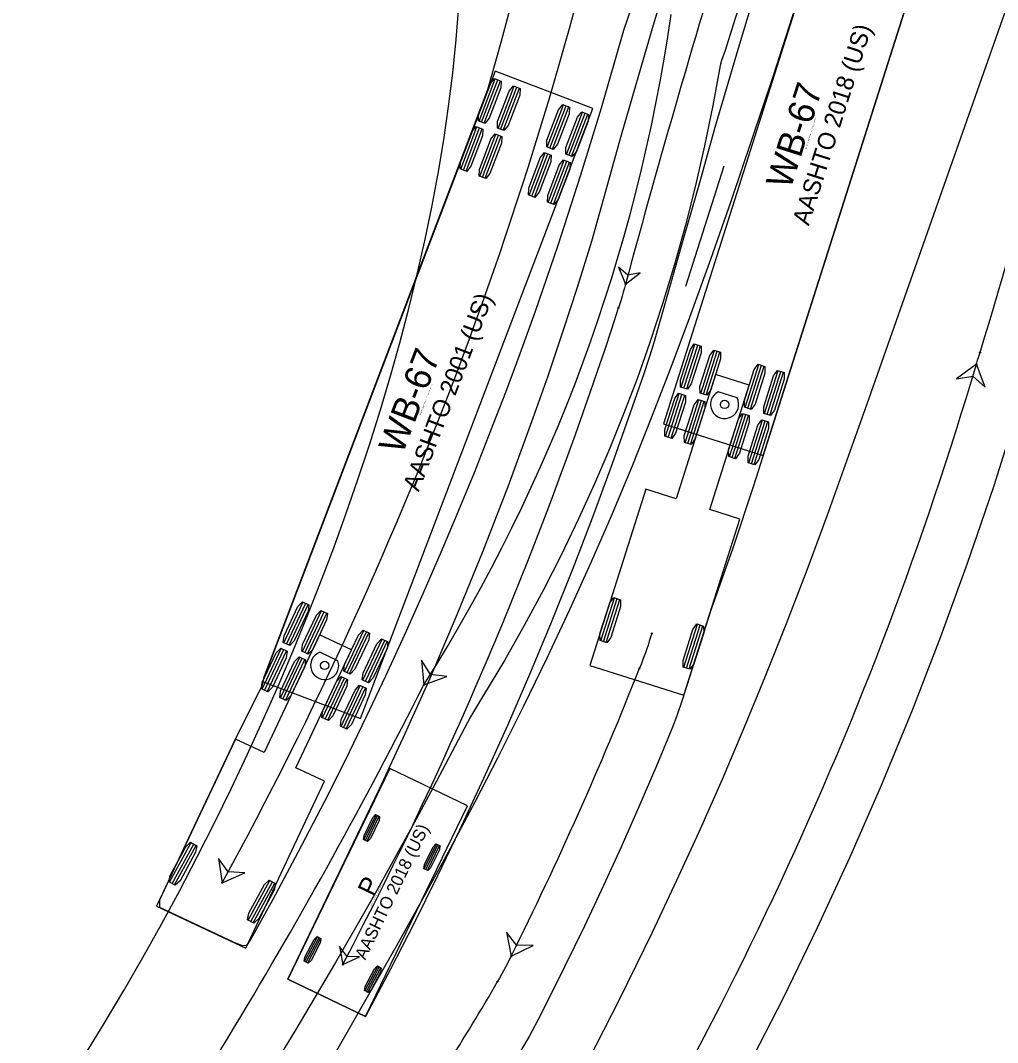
# Model space of a CAD drawing. Extents: x 2175591 to 2194071, y 76570 to 86955.
# Drawn here: x 2192866.1 to 2192945.4, y 86502.5 to 86585.5 of the extents above; entities that cross this region are included whole.
import ezdxf

# ---------------------------------------------------------------- set-up
doc = ezdxf.new("R2010")
doc.units = 0
doc.layers.add('-NOPLT', color=7, linetype='Continuous')
doc.layers.add('C-UTIL-STRM-TEXT', color=7, linetype='Continuous')

msp = doc.modelspace()

# ---------------------------------------------------------------- linework, layer by layer
at = {"layer": '-NOPLT'}
for p, q in [((2192934.321, 86603.271), (2192918.277, 86552.758)), ((2192926.378, 86550.185), (2192942.422, 86600.698)), ((2192919.723, 86555.726), (2192920.832, 86559.221)), ((2192919.941, 86555.657), (2192921.051, 86559.151)), ((2192920.159, 86555.587), (2192921.269, 86559.082)), ((2192921.295, 86555.227), (2192922.405, 86558.721)), ((2192921.514, 86555.157), (2192922.623, 86558.652)), ((2192921.732, 86555.088), (2192922.842, 86558.583)), ((2192924.901, 86554.081), (2192926.011, 86557.576)), ((2192925.119, 86554.012), (2192926.229, 86557.507)), ((2192925.338, 86553.943), (2192926.448, 86557.437)), ((2192922.505, 86556.766), (2192919.296, 86546.663)), ((2192925.237, 86555.898), (2192922.505, 86556.766)), ((2192926.473, 86553.582), (2192927.583, 86557.077)), ((2192926.692, 86553.513), (2192927.802, 86557.007)), ((2192926.91, 86553.443), (2192928.02, 86556.938)), ((2192922.029, 86545.795), (2192925.237, 86555.898)), ((2192918.451, 86551.723), (2192919.561, 86555.218)), ((2192918.669, 86551.654), (2192919.779, 86555.148)), ((2192918.888, 86551.584), (2192919.998, 86555.079)), ((2192924.251, 86554.856), (2192922.71, 86555.345)), ((2192920.024, 86551.224), (2192921.134, 86554.718)), ((2192920.242, 86551.154), (2192921.352, 86554.649)), ((2192920.46, 86551.085), (2192921.57, 86554.58)), ((2192923.629, 86550.078), (2192924.739, 86553.573)), ((2192923.848, 86550.009), (2192924.958, 86553.504)), ((2192924.066, 86549.94), (2192925.176, 86553.434)), ((2192925.202, 86549.579), (2192926.312, 86553.074)), ((2192918.277, 86552.758), (2192926.378, 86550.185)), ((2192925.42, 86549.51), (2192926.53, 86553.004)), ((2192925.639, 86549.44), (2192926.749, 86552.935)), ((2192926.378, 86550.185), (2192926.378, 86550.185)), ((2192916.85, 86547.44), (2192912.309, 86533.144)), ((2192919.296, 86546.663), (2192916.85, 86547.44)), ((2192924.475, 86545.018), (2192922.029, 86545.795)), ((2192919.934, 86530.722), (2192924.475, 86545.018)), ((2192913.184, 86535.14), (2192914.294, 86538.634)), ((2192913.402, 86535.07), (2192914.512, 86538.565)), ((2192913.621, 86535.001), (2192914.731, 86538.496)), ((2192919.935, 86532.995), (2192921.045, 86536.49)), ((2192920.153, 86532.926), (2192921.263, 86536.421)), ((2192920.372, 86532.857), (2192921.481, 86536.351)), ((2192912.309, 86533.144), (2192919.934, 86530.722)), ((2192919.934, 86530.722), (2192919.934, 86530.722))]:
    msp.add_line(p, q, dxfattribs=at)
for points in [[(2192871.345, 86466.137), (2192896.643, 86510.418), (2192898.913, 86514.495), (2192900.984, 86518.301), (2192903.014, 86522.13), (2192904.85, 86525.683), (2192906.941, 86529.855), (2192908.832, 86533.754), (2192910.67, 86537.678), (2192912.454, 86541.628), (2192914.05, 86545.295), (2192915.725, 86549.292), (2192917.344, 86553.311), (2192918.908, 86557.35), (2192920.424, 86561.41), (2192922.12, 86566.113), (2192923.768, 86570.834), (2192925.485, 86575.883), (2192927.166, 86580.945), (2192929.023, 86586.65), (2192934.286, 86603.16), (2192934.619, 86603.154), (2192938.432, 86601.945)], [(2192938.432, 86601.945), (2192942.245, 86600.734), (2192942.322, 86600.41), (2192925.589, 86547.713), (2192923.907, 86542.652), (2192922.131, 86537.623), (2192919.803, 86530.318), (2192919.366, 86529.059), (2192919.009, 86528.125), (2192917.734, 86525.045), (2192916.289, 86521.675), (2192914.804, 86518.323), (2192913.419, 86515.291), (2192911.857, 86511.973), (2192910.256, 86508.675), (2192908.313, 86504.802), (2192907.377, 86503.034), (2192906.183, 86501.03)], [(2192871.263, 86501.428), (2192872.891, 86504.08), (2192874.481, 86506.751), (2192876.032, 86509.44), (2192877.544, 86512.146), (2192879.016, 86514.867), (2192880.448, 86517.604), (2192881.84, 86520.353), (2192883.192, 86523.116), (2192884.503, 86525.889), (2192885.774, 86528.672), (2192887.003, 86531.464), (2192888.191, 86534.262), (2192889.339, 86537.066), (2192890.447, 86539.878), (2192891.512, 86542.694), (2192892.532, 86545.505), (2192893.478, 86548.231), (2192894.41, 86551.045), (2192895.305, 86553.895), (2192896.147, 86556.729), (2192896.874, 86559.322), (2192897.608, 86562.112), (2192898.289, 86564.895), (2192898.906, 86567.622), (2192899.472, 86570.348), (2192899.984, 86573.073), (2192900.441, 86575.796), (2192900.841, 86578.516), (2192901.181, 86581.232), (2192901.459, 86583.943), (2192901.674, 86586.647)], [(2192924.301, 86586.341), (2192923.809, 86584.698), (2192923.277, 86583.066), (2192922.996, 86582.254), (2192922.873, 86581.848), (2192922.283, 86578.581), (2192921.617, 86575.328), (2192920.876, 86572.092), (2192920.06, 86568.875), (2192919.17, 86565.678), (2192918.206, 86562.503), (2192917.169, 86559.351), (2192916.128, 86556.411), (2192915.017, 86553.48), (2192913.931, 86550.788), (2192912.685, 86547.878), (2192911.391, 86545.032), (2192909.976, 86542.093), (2192908.534, 86539.266), (2192906.982, 86536.383), (2192905.373, 86533.551), (2192903.684, 86530.731), (2192902.606, 86528.982), (2192901.106, 86526.099), (2192899.585, 86523.226), (2192898.042, 86520.365), (2192896.479, 86517.516), (2192894.895, 86514.678), (2192893.289, 86511.852), (2192891.664, 86509.038), (2192890.018, 86506.236), (2192888.351, 86503.446), (2192886.664, 86500.668)], [(2192917.333, 86535.745), (2192917.232, 86535.428), (2192917.128, 86535.111), (2192917.023, 86534.795), (2192916.914, 86534.479), (2192916.804, 86534.165), (2192916.69, 86533.852), (2192916.575, 86533.539), (2192916.456, 86533.227), (2192916.335, 86532.917)], [(2192905.912, 86509.534), (2192907.709, 86510.413), (2192906.357, 86510.43), (2192905.528, 86511.497), (2192905.912, 86509.534)], [(2192905.912, 86509.534), (2192905.763, 86509.236), (2192905.612, 86508.939), (2192905.459, 86508.643), (2192905.302, 86508.349), (2192905.143, 86508.056), (2192904.981, 86507.764), (2192904.817, 86507.474)]]:
    msp.add_lwpolyline(points, dxfattribs=at)
for points in [[(2192920.214, 86555.57), (2192919.668, 86555.743), (2192919.659, 86556.285), (2192920.459, 86558.801), (2192920.778, 86559.238), (2192921.323, 86559.065), (2192921.332, 86558.523), (2192920.533, 86556.007)], [(2192921.786, 86555.071), (2192921.241, 86555.244), (2192921.232, 86555.785), (2192922.031, 86558.301), (2192922.351, 86558.739), (2192922.896, 86558.565), (2192922.905, 86558.024), (2192922.106, 86555.508)], [(2192925.392, 86553.925), (2192924.847, 86554.099), (2192924.838, 86554.64), (2192925.637, 86557.156), (2192925.957, 86557.593), (2192926.502, 86557.42), (2192926.511, 86556.879), (2192925.712, 86554.363)], [(2192926.964, 86553.426), (2192926.419, 86553.599), (2192926.41, 86554.141), (2192927.21, 86556.657), (2192927.529, 86557.094), (2192928.074, 86556.921), (2192928.083, 86556.379), (2192927.284, 86553.863)], [(2192918.942, 86551.567), (2192918.397, 86551.74), (2192918.388, 86552.282), (2192919.187, 86554.798), (2192919.507, 86555.235), (2192920.052, 86555.062), (2192920.061, 86554.52), (2192919.262, 86552.004)], [(2192920.515, 86551.068), (2192919.969, 86551.241), (2192919.961, 86551.782), (2192920.76, 86554.298), (2192921.079, 86554.736), (2192921.625, 86554.562), (2192921.633, 86554.021), (2192920.834, 86551.505)], [(2192924.12, 86549.922), (2192923.575, 86550.096), (2192923.566, 86550.637), (2192924.366, 86553.153), (2192924.685, 86553.59), (2192925.23, 86553.417), (2192925.239, 86552.876), (2192924.44, 86550.36)], [(2192925.693, 86549.423), (2192925.148, 86549.596), (2192925.139, 86550.138), (2192925.938, 86552.654), (2192926.258, 86553.091), (2192926.803, 86552.918), (2192926.812, 86552.376), (2192926.013, 86549.86)], [(2192913.675, 86534.984), (2192913.13, 86535.157), (2192913.121, 86535.698), (2192913.92, 86538.214), (2192914.24, 86538.651), (2192914.785, 86538.478), (2192914.794, 86537.937), (2192913.994, 86535.421)], [(2192920.426, 86532.839), (2192919.881, 86533.013), (2192919.872, 86533.554), (2192920.671, 86536.07), (2192920.991, 86536.507), (2192921.536, 86536.334), (2192921.545, 86535.793), (2192920.745, 86533.277)], [(2192898.824, 86531.568), (2192900.701, 86532.257), (2192899.358, 86532.413), (2192898.643, 86533.56)], [(2192905.912, 86509.534), (2192907.709, 86510.413), (2192906.357, 86510.43), (2192905.528, 86511.497)]]:
    msp.add_lwpolyline(points, close=True, dxfattribs=at)
for centre, radius in [((2192923.236, 86554.33), 0.34), ((2192917.333, 86535.745), 0.0417), ((2192916.335, 86532.917), 0.0417), ((2192916.335, 86532.917), 0.0417), ((2192898.824, 86531.568), 0.0417), ((2192898.824, 86531.568), 0.0417), ((2192905.912, 86509.534), 0.0417), ((2192905.912, 86509.534), 0.0417), ((2192904.817, 86507.474), 0.0417), ((2192904.817, 86507.474), 0.0417)]:
    msp.add_circle(centre, radius, dxfattribs=at)
for centre, radius, start, end in [((2192781.745, 86605.676), 138.562, 327.66691, 351.82377), ((2192923.236, 86554.33), 1.143, 117.37883, 27.37883), ((2192635.9, 86643.909), 301.601, 333.54225, 338.40709), ((2192518.796, 86723.555), 425.77, 324.65596, 333.19742), ((2192758.857, 86591.644), 168.49, 324.61495, 330.02968)]:
    msp.add_arc(centre, radius, start, end, dxfattribs=at)
at = {"layer": 'C-UTIL-STRM-TEXT'}
for p, q in [((2192904.605, 86581.38), (2192885.742, 86531.85)), ((2192912.548, 86578.355), (2192904.605, 86581.38)), ((2192903.306, 86577.327), (2192904.611, 86580.754)), ((2192903.52, 86577.245), (2192904.825, 86580.672)), ((2192903.735, 86577.164), (2192905.04, 86580.59)), ((2192904.848, 86576.74), (2192906.153, 86580.166)), ((2192905.062, 86576.658), (2192906.367, 86580.085)), ((2192905.277, 86576.577), (2192906.581, 86580.003)), ((2192893.686, 86528.825), (2192912.548, 86578.355)), ((2192908.851, 86575.215), (2192910.156, 86578.642)), ((2192909.065, 86575.134), (2192910.37, 86578.56)), ((2192909.279, 86575.052), (2192910.584, 86578.479)), ((2192910.393, 86574.628), (2192911.698, 86578.055)), ((2192910.607, 86574.547), (2192911.912, 86577.973)), ((2192910.821, 86574.465), (2192912.126, 86577.892)), ((2192901.823, 86573.433), (2192903.128, 86576.86)), ((2192902.038, 86573.352), (2192903.342, 86576.778)), ((2192902.252, 86573.27), (2192903.557, 86576.697)), ((2192903.365, 86572.846), (2192904.67, 86576.272)), ((2192903.579, 86572.764), (2192904.884, 86576.191)), ((2192903.794, 86572.683), (2192905.099, 86576.109)), ((2192907.368, 86571.321), (2192908.673, 86574.748)), ((2192907.582, 86571.24), (2192908.887, 86574.666)), ((2192907.797, 86571.158), (2192909.101, 86574.585)), ((2192908.91, 86570.734), (2192910.215, 86574.161)), ((2192909.124, 86570.653), (2192910.429, 86574.079)), ((2192909.338, 86570.571), (2192910.643, 86573.998)), ((2192920.103, 86563.925), (2192923.204, 86573.687)), ((2192887.477, 86534.975), (2192889.041, 86538.292)), ((2192887.685, 86534.878), (2192889.248, 86538.194)), ((2192887.892, 86534.78), (2192889.455, 86538.097)), ((2192888.97, 86534.272), (2192890.533, 86537.589)), ((2192889.177, 86534.174), (2192890.74, 86537.491)), ((2192889.384, 86534.076), (2192890.948, 86537.393)), ((2192892.392, 86532.659), (2192893.955, 86535.975)), ((2192892.599, 86532.561), (2192894.163, 86535.878)), ((2192892.806, 86532.463), (2192894.37, 86535.78)), ((2192890.373, 86535.637), (2192885.861, 86526.064)), ((2192892.966, 86534.415), (2192890.373, 86535.637)), ((2192893.884, 86531.955), (2192895.448, 86535.272)), ((2192894.092, 86531.857), (2192895.655, 86535.174)), ((2192894.299, 86531.76), (2192895.862, 86535.076)), ((2192885.701, 86531.207), (2192887.264, 86534.523)), ((2192885.908, 86531.109), (2192887.471, 86534.425)), ((2192886.115, 86531.011), (2192887.679, 86534.328)), ((2192888.454, 86524.842), (2192892.966, 86534.415)), ((2192891.857, 86533.528), (2192890.395, 86534.217)), ((2192887.193, 86530.503), (2192888.757, 86533.82)), ((2192887.4, 86530.405), (2192888.964, 86533.722)), ((2192887.608, 86530.308), (2192889.171, 86533.624)), ((2192885.742, 86531.85), (2192893.686, 86528.825)), ((2192890.615, 86528.89), (2192892.179, 86532.206)), ((2192890.823, 86528.792), (2192892.386, 86532.109)), ((2192891.03, 86528.694), (2192892.593, 86532.011)), ((2192892.108, 86528.186), (2192893.671, 86531.503)), ((2192892.315, 86528.089), (2192893.878, 86531.405)), ((2192892.522, 86527.991), (2192894.086, 86531.307)), ((2192893.686, 86528.825), (2192893.686, 86528.825)), ((2192883.539, 86527.158), (2192877.143, 86513.59)), ((2192885.861, 86526.064), (2192883.539, 86527.158)), ((2192896.061, 86524.786), (2192887.789, 86507.681)), ((2192890.775, 86523.747), (2192888.454, 86524.842)), ((2192902.363, 86521.738), (2192896.061, 86524.786)), ((2192884.379, 86510.179), (2192890.775, 86523.747)), ((2192894.09, 86504.633), (2192902.363, 86521.738)), ((2192893.971, 86518.993), (2192894.951, 86521.018)), ((2192894.098, 86518.931), (2192895.077, 86520.957)), ((2192894.224, 86518.87), (2192895.204, 86520.896)), ((2192878.194, 86515.54), (2192879.956, 86518.756)), ((2192878.395, 86515.43), (2192880.157, 86518.646)), ((2192878.596, 86515.32), (2192880.358, 86518.536)), ((2192898.866, 86516.625), (2192899.846, 86518.651)), ((2192898.993, 86516.564), (2192899.972, 86518.59)), ((2192899.119, 86516.503), (2192900.099, 86518.528)), ((2192884.578, 86512.47), (2192886.336, 86515.687)), ((2192884.779, 86512.36), (2192886.537, 86515.577)), ((2192884.98, 86512.25), (2192886.738, 86515.467)), ((2192877.143, 86513.59), (2192884.379, 86510.179)), ((2192889.154, 86509.12), (2192890.201, 86511.111)), ((2192889.279, 86509.054), (2192890.326, 86511.046)), ((2192889.403, 86508.989), (2192890.45, 86510.98)), ((2192884.379, 86510.179), (2192884.379, 86510.179)), ((2192894.042, 86506.735), (2192895.088, 86508.727)), ((2192894.166, 86506.67), (2192895.212, 86508.662)), ((2192894.291, 86506.604), (2192895.337, 86508.597)), ((2192887.789, 86507.681), (2192894.09, 86504.633)), ((2192894.09, 86504.633), (2192894.09, 86504.633))]:
    msp.add_line(p, q, dxfattribs=at)
for points in [[(2192926.843, 86619.247), (2192915.025, 86584.675), (2192913.207, 86578.366), (2192911.551, 86572.946), (2192909.698, 86567.24), (2192907.852, 86561.882), (2192906.61, 86558.432), (2192905.446, 86555.309), (2192904.252, 86552.197), (2192902.902, 86548.788), (2192901.514, 86545.394), (2192900.22, 86542.322), (2192898.761, 86538.958), (2192897.402, 86535.914), (2192895.731, 86532.28), (2192894.161, 86528.967), (2192892.407, 86525.372), (2192890.76, 86522.096), (2192888.612, 86517.953), (2192886.566, 86514.133), (2192884.796, 86510.924), (2192884.399, 86510.394), (2192884.066, 86510.4), (2192883.445, 86510.642), (2192877.414, 86513.483), (2192877.412, 86514.125), (2192879.956, 86519.559), (2192883.512, 86527.096), (2192885.727, 86531.578), (2192885.883, 86532.221), (2192904.017, 86579.885), (2192905.097, 86583.733), (2192906.125, 86587.599)], [(2192912.156, 86501.045), (2192914.736, 86506.091), (2192917.378, 86511.477), (2192919.37, 86515.698), (2192921.17, 86519.639), (2192923.056, 86523.908), (2192924.887, 86528.2), (2192926.539, 86532.207), (2192928.264, 86536.542), (2192929.936, 86540.899), (2192931.557, 86545.275), (2192934.812, 86554.377), (2192949.166, 86595.214)], [(2192927.395, 86593.358), (2192924.407, 86583.504), (2192922.45, 86576.808), (2192921.207, 86572.323), (2192919.895, 86567.822), (2192917.405, 86559.06), (2192916.67, 86556.822), (2192915.581, 86553.638), (2192914.119, 86549.514), (2192912.485, 86545.095), (2192910.913, 86541.012), (2192909.161, 86536.639), (2192907.48, 86532.599), (2192905.611, 86528.274), (2192903.683, 86523.975), (2192901.695, 86519.703), (2192899.946, 86516.069), (2192898.015, 86512.178), (2192896.121, 86508.479), (2192894.094, 86504.64), (2192887.792, 86507.688), (2192895.243, 86523.125), (2192897.32, 86527.606), (2192899.331, 86532.118), (2192901.528, 86537.268), (2192903.638, 86542.453), (2192905.66, 86547.673), (2192907.706, 86553.237), (2192908.906, 86556.654), (2192910.174, 86560.397), (2192911.296, 86563.838), (2192912.473, 86567.592), (2192914.876, 86576.201), (2192917.396, 86584.885), (2192919.908, 86593.222)], [(2192955.877, 86586.569), (2192954.877, 86582.353), (2192953.921, 86578.47), (2192952.068, 86571.375), (2192950.271, 86564.955), (2192947.94, 86556.957), (2192946.984, 86553.764), (2192945.072, 86547.726), (2192944.016, 86544.565), (2192942.927, 86541.414), (2192940.763, 86535.466), (2192938.478, 86529.559), (2192937.226, 86526.47), (2192935.941, 86523.394), (2192933.408, 86517.589), (2192930.758, 86511.841), (2192927.989, 86506.145), (2192925.104, 86500.507)], [(2192915.194, 86564.092), (2192916.386, 86565.003), (2192915.39, 86564.816), (2192914.623, 86565.48), (2192915.194, 86564.092)], [(2192915.194, 86564.092), (2192915.107, 86563.771), (2192915.017, 86563.45), (2192914.925, 86563.129), (2192914.83, 86562.81), (2192914.732, 86562.491), (2192914.631, 86562.173)], [(2192943.673, 86557.592), (2192943.767, 86557.912), (2192943.864, 86558.231), (2192943.963, 86558.55)], [(2192943.673, 86557.592), (2192942.055, 86556.417), (2192943.389, 86556.634), (2192944.39, 86555.725), (2192943.673, 86557.592)], [(2192882.467, 86515.503), (2192884.296, 86516.311), (2192882.946, 86516.38), (2192882.159, 86517.479), (2192882.467, 86515.503)], [(2192892.246, 86508.858), (2192893.607, 86509.487), (2192892.594, 86509.522), (2192891.99, 86510.336), (2192892.246, 86508.858)]]:
    msp.add_lwpolyline(points, dxfattribs=at)
for points in [[(2192903.788, 86577.144), (2192903.253, 86577.347), (2192903.275, 86577.888), (2192904.214, 86580.355), (2192904.558, 86580.774), (2192905.093, 86580.57), (2192905.071, 86580.029), (2192904.131, 86577.562)], [(2192905.33, 86576.556), (2192904.795, 86576.76), (2192904.817, 86577.301), (2192905.756, 86579.768), (2192906.1, 86580.187), (2192906.635, 86579.983), (2192906.613, 86579.442), (2192905.673, 86576.975)], [(2192909.333, 86575.032), (2192908.798, 86575.236), (2192908.82, 86575.777), (2192909.759, 86578.244), (2192910.103, 86578.662), (2192910.637, 86578.459), (2192910.616, 86577.917), (2192909.676, 86575.45)], [(2192910.875, 86574.445), (2192910.34, 86574.648), (2192910.362, 86575.189), (2192911.301, 86577.656), (2192911.645, 86578.075), (2192912.179, 86577.871), (2192912.158, 86577.33), (2192911.218, 86574.863)], [(2192902.305, 86573.25), (2192901.77, 86573.453), (2192901.792, 86573.994), (2192902.731, 86576.462), (2192903.075, 86576.88), (2192903.61, 86576.676), (2192903.588, 86576.135), (2192902.649, 86573.668)], [(2192903.847, 86572.663), (2192903.312, 86572.866), (2192903.334, 86573.407), (2192904.273, 86575.874), (2192904.617, 86576.293), (2192905.152, 86576.089), (2192905.13, 86575.548), (2192904.19, 86573.081)], [(2192907.85, 86571.138), (2192907.315, 86571.342), (2192907.337, 86571.883), (2192908.276, 86574.35), (2192908.62, 86574.768), (2192909.155, 86574.565), (2192909.133, 86574.024), (2192908.193, 86571.556)], [(2192909.392, 86570.551), (2192908.857, 86570.754), (2192908.879, 86571.295), (2192909.818, 86573.763), (2192910.162, 86574.181), (2192910.697, 86573.977), (2192910.675, 86573.436), (2192909.735, 86570.969)], [(2192915.194, 86564.092), (2192916.386, 86565.003), (2192915.39, 86564.816), (2192914.623, 86565.48)], [(2192943.673, 86557.592), (2192942.055, 86556.417), (2192943.389, 86556.634), (2192944.39, 86555.725)], [(2192887.943, 86534.756), (2192887.426, 86535), (2192887.489, 86535.537), (2192888.615, 86537.925), (2192888.989, 86538.316), (2192889.507, 86538.072), (2192889.444, 86537.535), (2192888.318, 86535.147)], [(2192889.436, 86534.052), (2192888.918, 86534.296), (2192888.981, 86534.834), (2192890.107, 86537.222), (2192890.482, 86537.613), (2192890.999, 86537.369), (2192890.936, 86536.831), (2192889.81, 86534.443)], [(2192892.858, 86532.439), (2192892.34, 86532.683), (2192892.403, 86533.221), (2192893.529, 86535.609), (2192893.904, 86536), (2192894.421, 86535.756), (2192894.358, 86535.218), (2192893.233, 86532.83)], [(2192894.35, 86531.735), (2192893.833, 86531.979), (2192893.896, 86532.517), (2192895.022, 86534.905), (2192895.396, 86535.296), (2192895.914, 86535.052), (2192895.851, 86534.514), (2192894.725, 86532.126)], [(2192886.167, 86530.987), (2192885.649, 86531.231), (2192885.712, 86531.769), (2192886.838, 86534.157), (2192887.213, 86534.547), (2192887.73, 86534.304), (2192887.667, 86533.766), (2192886.541, 86531.378)], [(2192887.659, 86530.283), (2192887.142, 86530.527), (2192887.205, 86531.065), (2192888.33, 86533.453), (2192888.705, 86533.844), (2192889.223, 86533.6), (2192889.16, 86533.062), (2192888.034, 86530.674)], [(2192891.081, 86528.67), (2192890.564, 86528.914), (2192890.627, 86529.452), (2192891.753, 86531.84), (2192892.127, 86532.231), (2192892.645, 86531.987), (2192892.582, 86531.449), (2192891.456, 86529.061)], [(2192892.574, 86527.967), (2192892.056, 86528.21), (2192892.119, 86528.748), (2192893.245, 86531.136), (2192893.62, 86531.527), (2192894.137, 86531.283), (2192894.074, 86530.745), (2192892.948, 86528.357)], [(2192894.256, 86518.855), (2192893.94, 86519.008), (2192893.981, 86519.338), (2192894.687, 86520.796), (2192894.919, 86521.033), (2192895.235, 86520.881), (2192895.193, 86520.551), (2192894.488, 86519.093)], [(2192878.646, 86515.293), (2192878.144, 86515.568), (2192878.24, 86516.101), (2192879.508, 86518.416), (2192879.906, 86518.783), (2192880.408, 86518.508), (2192880.312, 86517.975), (2192879.043, 86515.66)], [(2192899.151, 86516.488), (2192898.835, 86516.641), (2192898.877, 86516.97), (2192899.582, 86518.429), (2192899.814, 86518.666), (2192900.13, 86518.513), (2192900.088, 86518.184), (2192899.383, 86516.725)], [(2192882.467, 86515.503), (2192884.296, 86516.311), (2192882.946, 86516.38), (2192882.159, 86517.479)], [(2192885.03, 86512.223), (2192884.528, 86512.497), (2192884.623, 86513.03), (2192885.889, 86515.347), (2192886.286, 86515.714), (2192886.788, 86515.44), (2192886.693, 86514.907), (2192885.427, 86512.59)], [(2192889.434, 86508.972), (2192889.124, 86509.136), (2192889.177, 86509.464), (2192889.93, 86510.898), (2192890.17, 86511.127), (2192890.481, 86510.964), (2192890.428, 86510.636), (2192889.674, 86509.202)], [(2192892.246, 86508.858), (2192893.607, 86509.487), (2192892.594, 86509.522), (2192891.99, 86510.336)], [(2192894.321, 86506.588), (2192894.011, 86506.751), (2192894.064, 86507.079), (2192894.817, 86508.514), (2192895.057, 86508.744), (2192895.367, 86508.58), (2192895.315, 86508.252), (2192894.562, 86506.818)]]:
    msp.add_lwpolyline(points, close=True, dxfattribs=at)
for centre, radius in [((2192915.194, 86564.092), 0.0417), ((2192915.194, 86564.092), 0.0417), ((2192914.631, 86562.173), 0.0417), ((2192914.631, 86562.173), 0.0417), ((2192943.963, 86558.55), 0.0417), ((2192943.963, 86558.55), 0.0417), ((2192943.673, 86557.592), 0.0417), ((2192943.673, 86557.592), 0.0417), ((2192890.782, 86533.141), 0.34), ((2192882.467, 86515.503), 0.0417), ((2192892.246, 86508.858), 0.0417)]:
    msp.add_circle(centre, radius, dxfattribs=at)
for centre, radius, start, end in [((2193752.897, 86337.713), 867.752, 160.665795, 164.87769), ((2192595.835, 86672.362), 326.746, 331.31037, 347.81974), ((2192560.662, 86677.393), 401.302, 342.77388, 348.50463), ((2192594.945, 86665.043), 335.83, 332.28517, 342.1628), ((2192651.949, 86643.846), 304.208, 326.59178, 343.52865), ((2192890.782, 86533.141), 1.143, 109.76073, 19.76073)]:
    msp.add_arc(centre, radius, start, end, dxfattribs=at)

# ---------------------------------------------------------------- texts
at = {"layer": '-NOPLT'}
for s, height, p in [('AASHTO 2018 (US)', 1.41667, (2192930.061, 86568.777)), ('WB-67', 2.125, (2192928.579, 86571.716)), ('(c) 2024 Transoft Solutions, Inc. All rights reserved.', 0.085, (2192929.863, 86575.056))]:
    msp.add_text(s, height=height, rotation=72.37883, dxfattribs=at).set_placement(p)
at = {"layer": 'C-UTIL-STRM-TEXT'}
for s, height, rotation, p in [('AASHTO 2001 (US)', 1.41667, 69.15153, (2192898.41, 86547.181)), ('WB-67', 2.125, 69.15153, (2192897.096, 86550.199)), ('(c) 2024 Transoft Solutions, Inc. All rights reserved.', 0.085, 69.15153, (2192898.565, 86553.461)), ('AASHTO 2018 (US)', 1, 64.19052, (2192894.075, 86509.183)), ('P', 1.5, 64.19052, (2192894.75, 86514.312)), ('(c) 2024 Transoft Solutions, Inc. All rights reserved.', 0.06, 64.19052, (2192894.568, 86513.59))]:
    msp.add_text(s, height=height, rotation=rotation, dxfattribs=at).set_placement(p)

doc.saveas('drawing.dxf')
